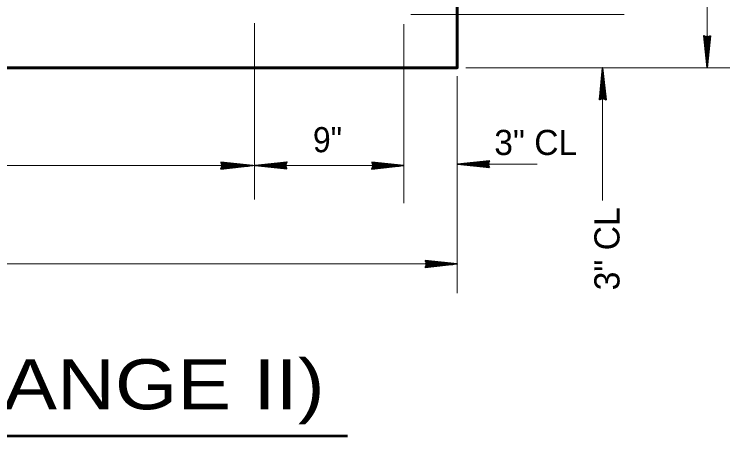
# Model space of a CAD drawing. Extents: x 4.49 to 7.69, y 0.28 to 2.27.
# Drawn here: x 6.0882 to 6.3252, y 1.2921 to 1.4317 of the extents above; entities that cross this region are included whole.
import ezdxf
from ezdxf.enums import TextEntityAlignment as Align

# ---------------------------------------------------------------- set-up
doc = ezdxf.new("R2010")
doc.units = 0
doc.header["$LTSCALE"] = 0.0033
doc.layers.add('1', color=7, linetype='Continuous', lineweight=35)

msp = doc.modelspace()

# ---------------------------------------------------------------- linework, layer by layer
at = {"layer": '1', "lineweight": 13}
for p, q in [((6.31775, 1.496667), (6.31775, 1.414)), ((6.2195, 1.431667), (6.290167, 1.431667)), ((6.16775, 1.42875), (6.16775, 1.370333)), ((6.21725, 1.428417), (6.21725, 1.369167)), ((6.23775, 1.414), (6.325167, 1.414)), ((6.234917, 1.41125), (6.234917, 1.339333)), ((6.283083, 1.37), (6.283083, 1.404083)), ((6.244917, 1.382), (6.261333, 1.382)), ((5.835917, 1.381583), (6.216917, 1.381583)), ((5.81825, 1.349), (6.234583, 1.349))]:
    msp.add_line(p, q, dxfattribs=at)
at = {"layer": '1'}
for p, q in [((6.317083, 1.424417), (6.317833, 1.417083)), ((6.31775, 1.424583), (6.31775, 1.414)), ((6.316667, 1.424333), (6.3175, 1.417)), ((6.316833, 1.424333), (6.317583, 1.417)), ((6.316917, 1.424333), (6.31775, 1.417)), ((6.318583, 1.424333), (6.317583, 1.4165)), ((6.318583, 1.424333), (6.31775, 1.4165)), ((6.31875, 1.424333), (6.317833, 1.4165)), ((6.31875, 1.424333), (6.317833, 1.4165)), ((6.318667, 1.424333), (6.317833, 1.4165)), ((6.283083, 1.403417), (6.283083, 1.414)), ((6.282083, 1.403667), (6.283, 1.4115)), ((6.282083, 1.403667), (6.283, 1.4115)), ((6.282167, 1.403667), (6.283, 1.4115)), ((6.28225, 1.403667), (6.283083, 1.4115)), ((6.28225, 1.403667), (6.28325, 1.4115)), ((6.28375, 1.403583), (6.283, 1.410917)), ((6.283917, 1.403667), (6.283083, 1.411)), ((6.284, 1.403667), (6.28325, 1.411)), ((6.284167, 1.403667), (6.283333, 1.411)), ((6.156833, 1.382583), (6.164667, 1.381667)), ((6.156833, 1.382583), (6.164667, 1.381667)), ((6.156833, 1.3825), (6.164667, 1.381667)), ((6.156833, 1.382417), (6.164667, 1.381583)), ((6.156833, 1.382417), (6.164667, 1.381417)), ((6.17825, 1.38075), (6.170417, 1.38175)), ((6.17825, 1.382667), (6.170917, 1.381833)), ((6.17825, 1.3825), (6.170917, 1.38175)), ((6.17825, 1.382417), (6.170917, 1.381583)), ((6.178333, 1.38225), (6.171, 1.3815)), ((6.206833, 1.382583), (6.214667, 1.381667)), ((6.206833, 1.382583), (6.214667, 1.381667)), ((6.206833, 1.3825), (6.214667, 1.381667)), ((6.206833, 1.382417), (6.214667, 1.381583)), ((6.206833, 1.382417), (6.214667, 1.381417)), ((6.245583, 1.382), (6.235, 1.382)), ((6.245333, 1.381167), (6.2375, 1.382167)), ((6.245333, 1.381167), (6.2375, 1.382)), ((6.245333, 1.381), (6.2375, 1.381917)), ((6.245333, 1.381), (6.2375, 1.381917)), ((6.245333, 1.381083), (6.2375, 1.381917)), ((6.245333, 1.383083), (6.238, 1.38225)), ((6.245333, 1.382917), (6.238, 1.382167)), ((6.245333, 1.382833), (6.238, 1.382)), ((6.245417, 1.382667), (6.238083, 1.381917)), ((6.156583, 1.381583), (6.167167, 1.381583)), ((6.15675, 1.380917), (6.164083, 1.381667)), ((6.156833, 1.38075), (6.164167, 1.381583)), ((6.156833, 1.380667), (6.164167, 1.381417)), ((6.156833, 1.3805), (6.164167, 1.381333)), ((6.1785, 1.381583), (6.167917, 1.381583)), ((6.17825, 1.38075), (6.170417, 1.381583)), ((6.17825, 1.380583), (6.170417, 1.3815)), ((6.17825, 1.380583), (6.170417, 1.3815)), ((6.17825, 1.380667), (6.170417, 1.3815)), ((6.206583, 1.381583), (6.217167, 1.381583)), ((6.20675, 1.380917), (6.214083, 1.381667)), ((6.206833, 1.38075), (6.214167, 1.381583)), ((6.206833, 1.380667), (6.214167, 1.381417)), ((6.206833, 1.3805), (6.214167, 1.381333)), ((6.224333, 1.349), (6.234917, 1.349)), ((6.2245, 1.348333), (6.231833, 1.349083)), ((6.224583, 1.35), (6.232417, 1.349083)), ((6.224583, 1.35), (6.232417, 1.349083)), ((6.224583, 1.349917), (6.232417, 1.349083)), ((6.224583, 1.349833), (6.232417, 1.349)), ((6.224583, 1.349833), (6.232417, 1.348833)), ((6.224583, 1.348167), (6.231917, 1.349)), ((6.224583, 1.348083), (6.231917, 1.348833)), ((6.224583, 1.347917), (6.231917, 1.34875))]:
    msp.add_line(p, q, dxfattribs=at)
at = {"layer": '1', "lineweight": 53}
msp.add_line((5.860917, 1.292083), (6.198583, 1.292083), dxfattribs=at)
at = {"layer": '1', "lineweight": 60}
msp.add_lwpolyline([(5.81825, 1.497333), (5.81825, 1.414), (6.234917, 1.414), (6.234917, 1.497333)], dxfattribs=at)
at = {"layer": '1'}
for points in [[(6.318833, 1.424583), (6.31775, 1.414), (6.316583, 1.424583), (6.31775, 1.424)], [(6.317833, 1.423833), (6.317917, 1.419167), (6.317833, 1.419167), (6.317833, 1.420083), (6.317917, 1.423833), (6.318, 1.420833), (6.318083, 1.424), (6.318167, 1.42175), (6.31825, 1.424), (6.318, 1.4205), (6.317833, 1.415833), (6.317583, 1.41675), (6.317583, 1.4155), (6.317583, 1.423833), (6.317417, 1.421417), (6.317417, 1.424), (6.317833, 1.418667), (6.317167, 1.424)], [(6.282, 1.403417), (6.283083, 1.414), (6.28425, 1.403417), (6.283083, 1.404)], [(6.283, 1.404167), (6.282917, 1.408833), (6.283, 1.408833), (6.283, 1.407917), (6.282917, 1.404167), (6.282833, 1.407167), (6.28275, 1.404), (6.282667, 1.40625), (6.282583, 1.404), (6.282833, 1.4075), (6.283, 1.412167), (6.28325, 1.41125), (6.28325, 1.4125), (6.28325, 1.404167), (6.283417, 1.406583), (6.283417, 1.404), (6.283, 1.409333), (6.283667, 1.404)], [(6.156583, 1.382667), (6.167167, 1.381583), (6.156583, 1.380417), (6.157167, 1.381583)], [(6.157333, 1.381667), (6.162, 1.38175), (6.162, 1.381667), (6.161083, 1.381667), (6.157333, 1.38175), (6.160333, 1.381833), (6.157167, 1.381917), (6.159417, 1.382), (6.157167, 1.382083), (6.160667, 1.381833), (6.165333, 1.381667), (6.164417, 1.381417), (6.165667, 1.381417), (6.157333, 1.381417), (6.15975, 1.38125), (6.157167, 1.38125), (6.1625, 1.381667), (6.157167, 1.381)], [(6.1785, 1.3805), (6.167917, 1.381583), (6.1785, 1.38275), (6.177917, 1.381583)], [(6.17775, 1.3815), (6.173083, 1.381417), (6.173083, 1.3815), (6.174, 1.3815), (6.17775, 1.381417), (6.17475, 1.381333), (6.177917, 1.38125), (6.175667, 1.381167), (6.177917, 1.381083), (6.174417, 1.381333), (6.16975, 1.3815), (6.170667, 1.38175), (6.169417, 1.38175), (6.17775, 1.38175), (6.175333, 1.381917), (6.177917, 1.381917), (6.172583, 1.3815), (6.177917, 1.382167)], [(6.206583, 1.382667), (6.217167, 1.381583), (6.206583, 1.380417), (6.207167, 1.381583)], [(6.207333, 1.381667), (6.212, 1.38175), (6.212, 1.381667), (6.211083, 1.381667), (6.207333, 1.38175), (6.210333, 1.381833), (6.207167, 1.381917), (6.209417, 1.382), (6.207167, 1.382083), (6.210667, 1.381833), (6.215333, 1.381667), (6.214417, 1.381417), (6.215667, 1.381417), (6.207333, 1.381417), (6.20975, 1.38125), (6.207167, 1.38125), (6.2125, 1.381667), (6.207167, 1.381)], [(6.245583, 1.380917), (6.235, 1.382), (6.245583, 1.383167), (6.245, 1.382)], [(6.244833, 1.381917), (6.240167, 1.381833), (6.240167, 1.381917), (6.241083, 1.381917), (6.244833, 1.381833), (6.241833, 1.38175), (6.245, 1.381667), (6.24275, 1.381583), (6.245, 1.3815), (6.2415, 1.38175), (6.236833, 1.381917), (6.23775, 1.382167), (6.2365, 1.382167), (6.244833, 1.382167), (6.242417, 1.382333), (6.245, 1.382333), (6.239667, 1.381917), (6.245, 1.382583)], [(6.224333, 1.350083), (6.234917, 1.349), (6.224333, 1.347833), (6.224917, 1.349)], [(6.225083, 1.349083), (6.22975, 1.349167), (6.22975, 1.349083), (6.228833, 1.349083), (6.225083, 1.349167), (6.228083, 1.34925), (6.224917, 1.349333), (6.227167, 1.349417), (6.224917, 1.3495), (6.228417, 1.34925), (6.233083, 1.349083), (6.232167, 1.348833), (6.233417, 1.348833), (6.225083, 1.348833), (6.2275, 1.348667), (6.224917, 1.348667), (6.23025, 1.349083), (6.224917, 1.348417)]]:
    msp.add_lwpolyline(points, close=True, dxfattribs=at)
for points in [[(6.317833, 1.423833), (6.318583, 1.42425), (6.318333, 1.424), (6.318, 1.423833), (6.318083, 1.423583), (6.318417, 1.42375), (6.317667, 1.423917), (6.317167, 1.424083), (6.31675, 1.424333)], [(6.283, 1.404167), (6.28225, 1.40375), (6.2825, 1.404), (6.282833, 1.404167), (6.28275, 1.404417), (6.282417, 1.40425), (6.283167, 1.404083), (6.283667, 1.403917), (6.284083, 1.403667)], [(6.157333, 1.381667), (6.156917, 1.382417), (6.157167, 1.382167), (6.157333, 1.381833), (6.157583, 1.381917), (6.157417, 1.38225), (6.15725, 1.3815), (6.157083, 1.381), (6.156833, 1.380583)], [(6.17775, 1.3815), (6.178167, 1.38075), (6.177917, 1.381), (6.17775, 1.381333), (6.1775, 1.38125), (6.177667, 1.380917), (6.177833, 1.381667), (6.178, 1.382167), (6.17825, 1.382583)], [(6.207333, 1.381667), (6.206917, 1.382417), (6.207167, 1.382167), (6.207333, 1.381833), (6.207583, 1.381917), (6.207417, 1.38225), (6.20725, 1.3815), (6.207083, 1.381), (6.206833, 1.380583)], [(6.244833, 1.381917), (6.24525, 1.381167), (6.245, 1.381417), (6.244833, 1.38175), (6.244583, 1.381667), (6.24475, 1.381333), (6.244917, 1.382083), (6.245083, 1.382583), (6.245333, 1.383)], [(6.225083, 1.349083), (6.224667, 1.349833), (6.224917, 1.349583), (6.225083, 1.34925), (6.225333, 1.349333), (6.225167, 1.349667), (6.225, 1.348917), (6.224833, 1.348417), (6.224583, 1.348)]]:
    msp.add_lwpolyline(points, dxfattribs=at)

# ---------------------------------------------------------------- texts
at = {"layer": '1', "width": 0.95}
msp.add_text('9"', height=0.008334, dxfattribs=at).set_placement((6.191917, 1.386), align=Align.CENTER)
at = {"layer": '1'}
msp.add_text('3" CL', height=0.008334, dxfattribs=at).set_placement((6.247167, 1.385083))
msp.add_text('3" CL', height=0.008334, rotation=90, dxfattribs=at).set_placement((6.288667, 1.34025))
at = {"layer": '1', "width": 1.2}
msp.add_text("SECTION 'B-B' (RANGE II)", height=0.01658, dxfattribs=at).set_placement((5.868917, 1.300833))

doc.saveas('drawing.dxf')
